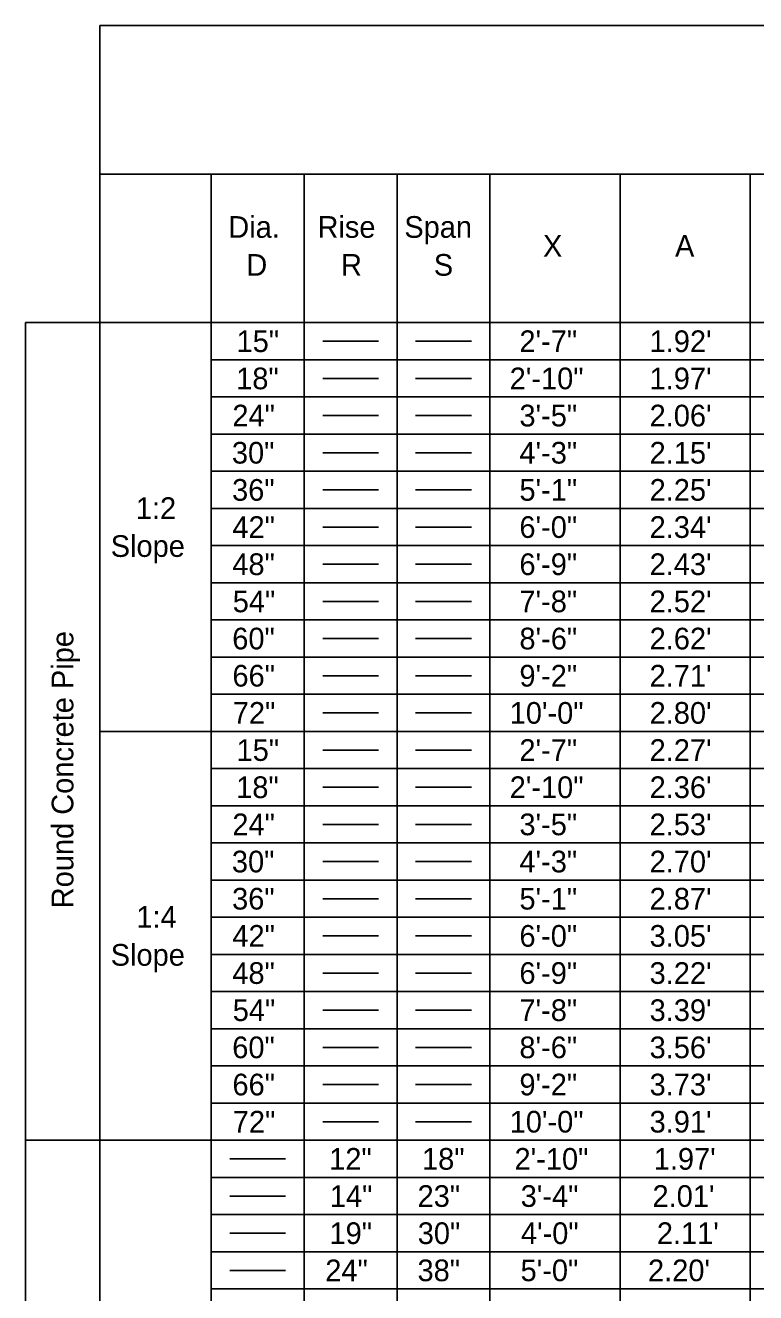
# Model space of a CAD drawing. Extents: x -1.3 to 14.6, y 0 to 8.4.
# Drawn here: x 1.7 to 4.058, y 4.338 to 8.43 of the extents above; entities that cross this region are included whole.
import ezdxf

# ---------------------------------------------------------------- set-up
doc = ezdxf.new("R2010")
doc.units = 0
doc.layers.add('Table', color=7, linetype='Continuous')

msp = doc.modelspace()

# ---------------------------------------------------------------- linework, layer by layer
at = {"layer": 'Table'}
for p, q in [((1.94, 8.43), (13.46, 8.43)), ((2.66, 7.41), (2.84, 7.41)), ((2.96, 7.41), (3.14, 7.41)), ((2.66, 7.29), (2.84, 7.29)), ((2.96, 7.29), (3.14, 7.29)), ((2.66, 7.17), (2.84, 7.17)), ((2.96, 7.17), (3.14, 7.17)), ((2.66, 7.05), (2.84, 7.05)), ((2.96, 7.05), (3.14, 7.05)), ((2.66, 6.93), (2.84, 6.93)), ((2.96, 6.93), (3.14, 6.93)), ((2.66, 6.81), (2.84, 6.81)), ((2.96, 6.81), (3.14, 6.81)), ((2.66, 6.69), (2.84, 6.69)), ((2.96, 6.69), (3.14, 6.69)), ((2.66, 6.57), (2.84, 6.57)), ((2.96, 6.57), (3.14, 6.57)), ((2.66, 6.45), (2.84, 6.45)), ((2.96, 6.45), (3.14, 6.45)), ((2.66, 6.33), (2.84, 6.33)), ((2.96, 6.33), (3.14, 6.33)), ((2.66, 6.21), (2.84, 6.21)), ((2.96, 6.21), (3.14, 6.21)), ((2.66, 6.09), (2.84, 6.09)), ((2.96, 6.09), (3.14, 6.09)), ((2.66, 5.97), (2.84, 5.97)), ((2.96, 5.97), (3.14, 5.97)), ((2.66, 5.85), (2.84, 5.85)), ((2.96, 5.85), (3.14, 5.85)), ((2.66, 5.73), (2.84, 5.73)), ((2.96, 5.73), (3.14, 5.73)), ((2.66, 5.61), (2.84, 5.61)), ((2.96, 5.61), (3.14, 5.61)), ((2.66, 5.49), (2.84, 5.49)), ((2.96, 5.49), (3.14, 5.49)), ((2.66, 5.37), (2.84, 5.37)), ((2.96, 5.37), (3.14, 5.37)), ((2.66, 5.25), (2.84, 5.25)), ((2.96, 5.25), (3.14, 5.25)), ((2.66, 5.13), (2.84, 5.13)), ((2.96, 5.13), (3.14, 5.13)), ((2.66, 5.01), (2.84, 5.01)), ((2.96, 5.01), (3.14, 5.01)), ((2.66, 4.89), (2.84, 4.89)), ((2.96, 4.89), (3.14, 4.89)), ((2.36, 4.77), (2.54, 4.77)), ((2.36, 4.65), (2.54, 4.65)), ((2.36, 4.53), (2.54, 4.53)), ((2.36, 4.41), (2.54, 4.41))]:
    msp.add_line(p, q, dxfattribs=at)
for points in [[(1.94, 8.43), (1.94, 7.83), (1.94, 7.47), (1.94, 6.15), (1.94, 4.83), (1.94, 3.51), (1.94, 2.19)], [(13.46, 7.95), (11.78, 7.95), (10.1, 7.95), (8.42, 7.95), (8.06, 7.95), (6.38, 7.95), (6.02, 7.95), (5.66, 7.95), (5.42, 7.95), (4.94, 7.95), (4.52, 7.95), (4.04, 7.95), (3.62, 7.95), (3.2, 7.95), (2.9, 7.95), (2.6, 7.95), (2.3, 7.95), (1.94, 7.95)], [(2.3, 7.95), (2.3, 7.47), (2.3, 7.35), (2.3, 7.23), (2.3, 7.11), (2.3, 6.99), (2.3, 6.87), (2.3, 6.75), (2.3, 6.63), (2.3, 6.51), (2.3, 6.39), (2.3, 6.27), (2.3, 6.15), (2.3, 6.03), (2.3, 5.91), (2.3, 5.79), (2.3, 5.67), (2.3, 5.55), (2.3, 5.43), (2.3, 5.31), (2.3, 5.19), (2.3, 5.07), (2.3, 4.95), (2.3, 4.83), (2.3, 4.71), (2.3, 4.59), (2.3, 4.47), (2.3, 4.35), (2.3, 4.23)], [(2.6, 7.95), (2.6, 7.47), (2.6, 7.35), (2.6, 7.23), (2.6, 7.11), (2.6, 6.99), (2.6, 6.87), (2.6, 6.75), (2.6, 6.63), (2.6, 6.51), (2.6, 6.39), (2.6, 6.27), (2.6, 6.15), (2.6, 6.03), (2.6, 5.91), (2.6, 5.79), (2.6, 5.67), (2.6, 5.55), (2.6, 5.43), (2.6, 5.31), (2.6, 5.19), (2.6, 5.07), (2.6, 4.95), (2.6, 4.83), (2.6, 4.71), (2.6, 4.59), (2.6, 4.47), (2.6, 4.35), (2.6, 4.23)], [(2.9, 7.95), (2.9, 7.47), (2.9, 7.35), (2.9, 7.23), (2.9, 7.11), (2.9, 6.99), (2.9, 6.87), (2.9, 6.75), (2.9, 6.63), (2.9, 6.51), (2.9, 6.39), (2.9, 6.27), (2.9, 6.15), (2.9, 6.03), (2.9, 5.91), (2.9, 5.79), (2.9, 5.67), (2.9, 5.55), (2.9, 5.43), (2.9, 5.31), (2.9, 5.19), (2.9, 5.07), (2.9, 4.95), (2.9, 4.83), (2.9, 4.71), (2.9, 4.59), (2.9, 4.47), (2.9, 4.35), (2.9, 4.23)], [(3.2, 7.95), (3.2, 7.47), (3.2, 7.35), (3.2, 7.23), (3.2, 7.11), (3.2, 6.99), (3.2, 6.87), (3.2, 6.75), (3.2, 6.63), (3.2, 6.51), (3.2, 6.39), (3.2, 6.27), (3.2, 6.15), (3.2, 6.03), (3.2, 5.91), (3.2, 5.79), (3.2, 5.67), (3.2, 5.55), (3.2, 5.43), (3.2, 5.31), (3.2, 5.19), (3.2, 5.07), (3.2, 4.95), (3.2, 4.83), (3.2, 4.71), (3.2, 4.59), (3.2, 4.47), (3.2, 4.35), (3.2, 4.23)], [(3.62, 7.95), (3.62, 7.47), (3.62, 7.35), (3.62, 7.23), (3.62, 7.11), (3.62, 6.99), (3.62, 6.87), (3.62, 6.75), (3.62, 6.63), (3.62, 6.51), (3.62, 6.39), (3.62, 6.27), (3.62, 6.15), (3.62, 6.03), (3.62, 5.91), (3.62, 5.79), (3.62, 5.67), (3.62, 5.55), (3.62, 5.43), (3.62, 5.31), (3.62, 5.19), (3.62, 5.07), (3.62, 4.95), (3.62, 4.83), (3.62, 4.71), (3.62, 4.59), (3.62, 4.47), (3.62, 4.35), (3.62, 4.23)], [(4.04, 7.95), (4.04, 7.47), (4.04, 7.35), (4.04, 7.23), (4.04, 7.11), (4.04, 6.99), (4.04, 6.87), (4.04, 6.75), (4.04, 6.63), (4.04, 6.51), (4.04, 6.39), (4.04, 6.27), (4.04, 6.15), (4.04, 6.03), (4.04, 5.91), (4.04, 5.79), (4.04, 5.67), (4.04, 5.55), (4.04, 5.43), (4.04, 5.31), (4.04, 5.19), (4.04, 5.07), (4.04, 4.95), (4.04, 4.83), (4.04, 4.71), (4.04, 4.59), (4.04, 4.47), (4.04, 4.35), (4.04, 4.23)], [(1.7, 7.47), (1.94, 7.47), (2.3, 7.47), (2.6, 7.47), (2.9, 7.47), (3.2, 7.47), (3.62, 7.47), (4.04, 7.47), (4.52, 7.47)], [(1.7, 7.47), (1.7, 4.83), (1.7, 2.19)], [(2.3, 7.35), (2.6, 7.35), (2.9, 7.35), (3.2, 7.35), (3.62, 7.35), (4.04, 7.35), (4.52, 7.35)], [(2.3, 7.23), (2.6, 7.23), (2.9, 7.23), (3.2, 7.23), (3.62, 7.23), (4.04, 7.23), (4.52, 7.23)], [(2.3, 7.11), (2.6, 7.11), (2.9, 7.11), (3.2, 7.11), (3.62, 7.11), (4.04, 7.11), (4.52, 7.11)], [(2.3, 6.99), (2.6, 6.99), (2.9, 6.99), (3.2, 6.99), (3.62, 6.99), (4.04, 6.99), (4.52, 6.99)], [(2.3, 6.87), (2.6, 6.87), (2.9, 6.87), (3.2, 6.87), (3.62, 6.87), (4.04, 6.87), (4.52, 6.87)], [(2.3, 6.75), (2.6, 6.75), (2.9, 6.75), (3.2, 6.75), (3.62, 6.75), (4.04, 6.75), (4.52, 6.75)], [(2.3, 6.63), (2.6, 6.63), (2.9, 6.63), (3.2, 6.63), (3.62, 6.63), (4.04, 6.63), (4.52, 6.63)], [(2.3, 6.51), (2.6, 6.51), (2.9, 6.51), (3.2, 6.51), (3.62, 6.51), (4.04, 6.51), (4.52, 6.51)], [(2.3, 6.39), (2.6, 6.39), (2.9, 6.39), (3.2, 6.39), (3.62, 6.39), (4.04, 6.39), (4.52, 6.39)], [(2.3, 6.27), (2.6, 6.27), (2.9, 6.27), (3.2, 6.27), (3.62, 6.27), (4.04, 6.27), (4.52, 6.27)], [(1.94, 6.15), (2.3, 6.15), (2.6, 6.15), (2.9, 6.15), (3.2, 6.15), (3.62, 6.15), (4.04, 6.15), (4.52, 6.15)], [(2.3, 6.03), (2.6, 6.03), (2.9, 6.03), (3.2, 6.03), (3.62, 6.03), (4.04, 6.03), (4.52, 6.03)], [(2.3, 5.91), (2.6, 5.91), (2.9, 5.91), (3.2, 5.91), (3.62, 5.91), (4.04, 5.91), (4.52, 5.91)], [(2.3, 5.79), (2.6, 5.79), (2.9, 5.79), (3.2, 5.79), (3.62, 5.79), (4.04, 5.79), (4.52, 5.79)], [(2.3, 5.67), (2.6, 5.67), (2.9, 5.67), (3.2, 5.67), (3.62, 5.67), (4.04, 5.67), (4.52, 5.67)], [(2.3, 5.55), (2.6, 5.55), (2.9, 5.55), (3.2, 5.55), (3.62, 5.55), (4.04, 5.55), (4.52, 5.55)], [(2.3, 5.43), (2.6, 5.43), (2.9, 5.43), (3.2, 5.43), (3.62, 5.43), (4.04, 5.43), (4.52, 5.43)], [(2.3, 5.31), (2.6, 5.31), (2.9, 5.31), (3.2, 5.31), (3.62, 5.31), (4.04, 5.31), (4.52, 5.31)], [(2.3, 5.19), (2.6, 5.19), (2.9, 5.19), (3.2, 5.19), (3.62, 5.19), (4.04, 5.19), (4.52, 5.19)], [(2.3, 5.07), (2.6, 5.07), (2.9, 5.07), (3.2, 5.07), (3.62, 5.07), (4.04, 5.07), (4.52, 5.07)], [(2.3, 4.95), (2.6, 4.95), (2.9, 4.95), (3.2, 4.95), (3.62, 4.95), (4.04, 4.95), (4.52, 4.95)], [(1.7, 4.83), (1.94, 4.83), (2.3, 4.83), (2.6, 4.83), (2.9, 4.83), (3.2, 4.83), (3.62, 4.83), (4.04, 4.83), (4.52, 4.83)], [(2.3, 4.71), (2.6, 4.71), (2.9, 4.71), (3.2, 4.71), (3.62, 4.71), (4.04, 4.71), (4.52, 4.71)], [(2.3, 4.59), (2.6, 4.59), (2.9, 4.59), (3.2, 4.59), (3.62, 4.59), (4.04, 4.59), (4.52, 4.59)], [(2.3, 4.47), (2.6, 4.47), (2.9, 4.47), (3.2, 4.47), (3.62, 4.47), (4.04, 4.47), (4.52, 4.47)], [(2.3, 4.35), (2.6, 4.35), (2.9, 4.35), (3.2, 4.35), (3.62, 4.35), (4.04, 4.35), (4.52, 4.35)]]:
    msp.add_lwpolyline(points, dxfattribs=at)

# ---------------------------------------------------------------- texts
for s, p in [('Dia.', (2.3552, 7.744)), ('Rise', (2.6431, 7.744)), ('Span', (2.9234, 7.744)), ('X', (3.3712, 7.6828)), ('A', (3.7975, 7.6828)), ('D', (2.4134, 7.6215)), ('R', (2.7192, 7.6215)), ('S', (3.0186, 7.6215)), ('1:2', (2.0566, 6.8362)), ('Slope', (1.9756, 6.7137)), ('1:4', (2.0583, 5.5162)), ('Slope', (1.9756, 5.3937))]:
    msp.add_text(s, height=0.07, dxfattribs=at).set_placement(p)
for s, rotation, p in [('15"', 0, (2.3819, 7.375)), ('2\'-7"', 0, (3.2951, 7.375)), ("1.92'", 0, (3.7154, 7.375)), ('18"', 0, (2.3807, 7.255)), ('2\'-10"', 0, (3.2637, 7.255)), ("1.97'", 0, (3.7154, 7.255)), ('24"', 0, (2.3684, 7.135)), ('3\'-5"', 0, (3.2951, 7.135)), ("2.06'", 0, (3.7154, 7.135)), ('30"', 0, (2.3668, 7.015)), ('4\'-3"', 0, (3.2951, 7.015)), ("2.15'", 0, (3.7154, 7.015)), ('36"', 0, (2.3674, 6.895)), ('5\'-1"', 0, (3.2951, 6.895)), ("2.25'", 0, (3.7154, 6.895)), ('42"', 0, (2.3684, 6.775)), ('6\'-0"', 0, (3.2951, 6.775)), ("2.34'", 0, (3.7154, 6.775)), ('48"', 0, (2.3682, 6.655)), ('6\'-9"', 0, (3.2951, 6.655)), ("2.43'", 0, (3.7154, 6.655)), ('54"', 0, (2.3695, 6.535)), ('7\'-8"', 0, (3.2951, 6.535)), ("2.52'", 0, (3.7154, 6.535)), ('Round Concrete Pipe', 90, (1.855, 5.5792)), ('60"', 0, (2.368, 6.415)), ('8\'-6"', 0, (3.2951, 6.415)), ("2.62'", 0, (3.7154, 6.415)), ('66"', 0, (2.3686, 6.295)), ('9\'-2"', 0, (3.2951, 6.295)), ("2.71'", 0, (3.7154, 6.295)), ('72"', 0, (2.3697, 6.175)), ('10\'-0"', 0, (3.2637, 6.175)), ("2.80'", 0, (3.7154, 6.175)), ('15"', 0, (2.3819, 6.055)), ('2\'-7"', 0, (3.2951, 6.055)), ("2.27'", 0, (3.7154, 6.055)), ('18"', 0, (2.3807, 5.935)), ('2\'-10"', 0, (3.2637, 5.935)), ("2.36'", 0, (3.7154, 5.935)), ('24"', 0, (2.3684, 5.815)), ('3\'-5"', 0, (3.2951, 5.815)), ("2.53'", 0, (3.7154, 5.815)), ('30"', 0, (2.3668, 5.695)), ('4\'-3"', 0, (3.2951, 5.695)), ("2.70'", 0, (3.7154, 5.695)), ('36"', 0, (2.3674, 5.575)), ('5\'-1"', 0, (3.2951, 5.575)), ("2.87'", 0, (3.7154, 5.575)), ('42"', 0, (2.3684, 5.455)), ('6\'-0"', 0, (3.2951, 5.455)), ("3.05'", 0, (3.7154, 5.455)), ('48"', 0, (2.3682, 5.335)), ('6\'-9"', 0, (3.2951, 5.335)), ("3.22'", 0, (3.7154, 5.335)), ('54"', 0, (2.3695, 5.215)), ('7\'-8"', 0, (3.2951, 5.215)), ("3.39'", 0, (3.7154, 5.215)), ('60"', 0, (2.368, 5.095)), ('8\'-6"', 0, (3.2951, 5.095)), ("3.56'", 0, (3.7154, 5.095)), ('66"', 0, (2.3686, 4.975)), ('9\'-2"', 0, (3.2951, 4.975)), ("3.73'", 0, (3.7154, 4.975)), ('72"', 0, (2.3697, 4.855)), ('10\'-0"', 0, (3.2637, 4.855)), ("3.91'", 0, (3.7154, 4.855)), ('12"', 0, (2.6809, 4.735)), ('18"', 0, (2.9807, 4.735)), ('2\'-10"', 0, (3.2793, 4.735)), ("1.97'", 0, (3.7287, 4.735)), ('14"', 0, (2.683, 4.615)), ('23"', 0, (2.9663, 4.615)), ('3\'-4"', 0, (3.2992, 4.615)), ("2.01'", 0, (3.7248, 4.615)), ('19"', 0, (2.682, 4.495)), ('30"', 0, (2.9668, 4.495)), ('4\'-0"', 0, (3.2999, 4.495)), ("2.11'", 0, (3.7388, 4.495)), ('24"', 0, (2.6684, 4.375)), ('38"', 0, (2.9661, 4.375)), ('5\'-0"', 0, (3.2988, 4.375)), ("2.20'", 0, (3.7103, 4.375))]:
    msp.add_text(s, height=0.07, rotation=rotation, dxfattribs=at).set_placement(p)

doc.saveas('drawing.dxf')
